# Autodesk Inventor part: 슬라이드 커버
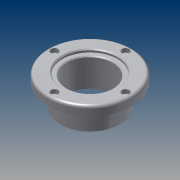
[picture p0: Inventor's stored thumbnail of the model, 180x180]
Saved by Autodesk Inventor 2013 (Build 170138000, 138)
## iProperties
Created: 2013-06
Part Number: 슬라이드 커버
Document SubType Name: Modeling
Designer: SeoGD™[esajin.kr]
Density: 2.71 g/cm^3
Material: 알루미늄 6061
Mass: 205.887 g
Surface Area: 227.998 cm^2
Volume: 75.9731 cm^3
Author: SeoGD™[esajin.kr]
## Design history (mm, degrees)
sketch "스케치1"
  geometry: C1 r 46 at (0, -39.25) reference; C2 r 32.5 at (0, -39.25) reference; 1 further point
  node "참조1"
  node "참조2"
extrude "돌출1" new body sketch "스케치1" distance "d0" = 10; taper "d1" = 0 deg
extrude "돌출2" join sketch "스케치1" distance "d2" = 25; taper "d3" = 0 deg
hole "구멍1" diameter "d6" = 50; stored, may be unused: countersink angle "d10" = 90 deg, drill point angle "d12" = 118 deg; dims "d4" = 10, "d5" = 10, "d7" = 6, "d8" = 4, "d9" = 2, "d11" = 8
sketch "스케치2"
  geometry: C1 r 46 at (0, 0) reference; C2 r 1.621 at (0, 39) reference; C3 r 1.621 at (39, 0) reference; C4 r 1.621 at (0, -39) reference; C5 r 1.621 at (-39, 0) reference; C6 r 33.5 at (0, 0) reference; 1 further point
hole "구멍2" sketch "스케치2" at (0, 39) diameter "d13" = 4.5; stored, may be unused: countersink angle "d17" = 90 deg, drill point angle "d19" = 118 deg; dims "d14" = 6, "d15" = 8, "d16" = 4.4, "d18" = 8
fillet "모깎기1" dims "d23" = 3
chamfer "모따기1" distance "d24" = 1; stored, may be unused: second distance "d25" = 2, angle "d26" = 45 deg
sketch "스케치3"
  geometry: C1 r 25 at (39, 0) reference; C2 r 30 at (39, 0); 1 further point
  constraints: 1 centre point, 1 coincident
  dimensions: "d27" = 60 diameter of C2
extrude "돌출3" cut sketch "스케치3" distance "d28" = 3; taper "d29" = 0 deg
chamfer "모따기2" distance "d30" = 1; stored, may be unused: second distance "d31" = 2, angle "d32" = 45 deg
node "솔리드1"
pattern_circular "원형 패턴1" dims angle "d21" = 360 deg
node "참조3"
